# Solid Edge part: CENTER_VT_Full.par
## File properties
Author: haileyy
Template: ansi part.par
Last saved by: haileyy
Revision: 2
Application: Solid Edge
Accuracy: 0.990
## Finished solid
Body 1: solid body, 79 faces, 230 edges, 152 vertices.
  Faces by surface: plane 60, cylinder 16, swept 3
  Edges by curve: line 192, circle 32, spline 6
Bounding box of the edges (mm; curved faces can reach further): 304.516 x 36.587 x 3.175, from (-131.5411, 167.8111, -3.175) to (172.9749, 204.3986, 0).
Cylindrical faces by radius (mm): R1.5875 x1, R6.35 x10, R6.985 x1, R166.2748 x1, R225.1567 x1, R530.0094 x1, R613.9774 x1
Planar faces by outward normal: +x 8, +y 5, +z 1, -x 7, -y 4, -z 1, oblique 34
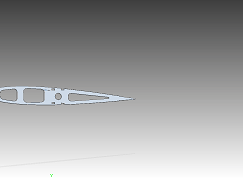
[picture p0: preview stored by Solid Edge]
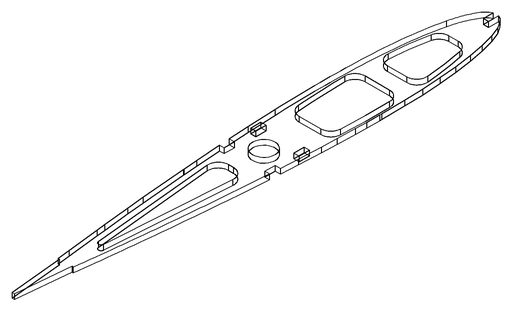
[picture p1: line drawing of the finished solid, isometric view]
